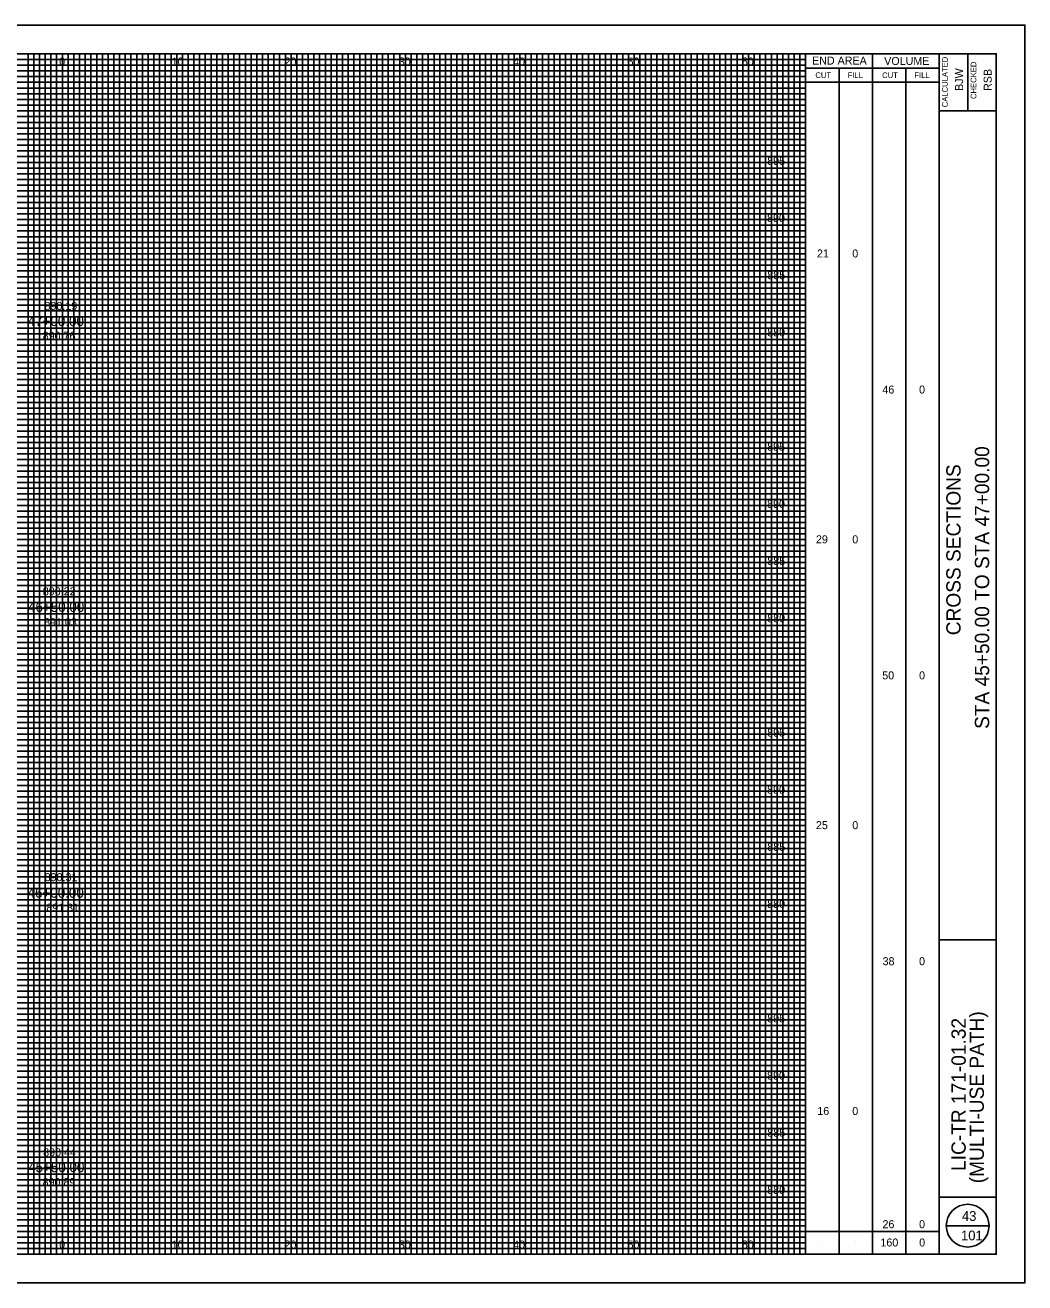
# Model space of a CAD drawing. Extents: x -10 to 160, y -2 to 2522.
# Drawn here: x 72.6 to 160, y 1722.5 to 1832.5 of the extents above; entities that cross this region are included whole.
import ezdxf

# ---------------------------------------------------------------- set-up
doc = ezdxf.new("R2010")
doc.units = 0
for name, color, linetype in [('GK_Cells', 7, 'Continuous'), ('GK_Patterns', 7, 'Continuous'), ('TX_P_10', 7, 'Continuous'), ('TX_X_10', 7, 'Continuous'), ('XS_P_Finished_Grade_Seeded', 7, 'Continuous'), ('XS_P_Pavt_Surface', 7, 'Continuous'), ('XS_P_Subgrade', 7, 'Continuous'), ('XS_X_Ground_Line', 7, 'Continuous')]:
    doc.layers.add(name, color=color, linetype=linetype)

msp = doc.modelspace()

# ---------------------------------------------------------------- linework, layer by layer
at = {"layer": 'GK_Cells'}
msp.add_lwpolyline([(-10, 1722.5), (160, 1722.5), (160, 1832.5), (-10, 1832.5)], close=True, dxfattribs=at)
at = {"layer": 'TX_P_10'}
for p, q in [((140.83, 1725), (140.83, 1830)), ((146.67, 1725), (146.67, 1830)), ((140.83, 1828.75), (152.5, 1828.75)), ((143.75, 1725), (143.75, 1828.75)), ((149.58, 1725), (149.58, 1828.75)), ((140.83, 1827.5), (152.5, 1827.5)), ((153.12, 1727.5), (156.88, 1727.5)), ((140.83, 1727), (152.5, 1727)), ((142.29, 1726), (142.29, 1726)), ((145.21, 1726), (145.21, 1726)), ((148.12, 1726), (148.12, 1726)), ((151.04, 1726), (151.04, 1726))]:
    msp.add_line(p, q, dxfattribs=at)
msp.add_circle((155, 1727.5), 1.87, dxfattribs=at)
at = {"layer": 'TX_X_10'}
for p, q in [((75.83, 1725), (75.83, 1830)), ((80.83, 1725), (80.83, 1830)), ((85.83, 1725), (85.83, 1830)), ((90.83, 1725), (90.83, 1830)), ((95.83, 1725), (95.83, 1830)), ((100.83, 1725), (100.83, 1830)), ((105.83, 1725), (105.83, 1830)), ((110.83, 1725), (110.83, 1830)), ((115.83, 1725), (115.83, 1830)), ((120.83, 1725), (120.83, 1830)), ((125.83, 1725), (125.83, 1830)), ((130.83, 1725), (130.83, 1830)), ((135.83, 1725), (135.83, 1830)), ((5.83, 1825), (140.83, 1825)), ((5.83, 1820), (140.83, 1820)), ((5.83, 1815), (140.83, 1815)), ((5.83, 1810), (140.83, 1810)), ((5.83, 1805), (140.83, 1805)), ((5.83, 1800), (140.83, 1800)), ((5.83, 1795), (140.83, 1795)), ((5.83, 1790), (140.83, 1790)), ((5.83, 1785), (140.83, 1785)), ((5.83, 1780), (140.83, 1780)), ((5.83, 1775), (140.83, 1775)), ((5.83, 1770), (140.83, 1770)), ((5.83, 1765), (140.83, 1765)), ((5.83, 1760), (140.83, 1760)), ((5.83, 1755), (140.83, 1755)), ((5.83, 1750), (140.83, 1750)), ((5.83, 1745), (140.83, 1745)), ((5.83, 1740), (140.83, 1740)), ((5.83, 1735), (140.83, 1735)), ((5.83, 1730), (140.83, 1730))]:
    msp.add_line(p, q, dxfattribs=at)
at = {"layer": 'XS_P_Pavt_Surface'}
for p, q in [((152.5, 1725), (152.5, 1830)), ((155, 1830), (155, 1825)), ((152.5, 1825), (157.5, 1825)), ((152.5, 1752.5), (157.5, 1752.5)), ((152.5, 1730), (157.5, 1730))]:
    msp.add_line(p, q, dxfattribs=at)
msp.add_lwpolyline([(0, 1830), (157.5, 1830), (157.5, 1725), (0, 1725)], close=True, dxfattribs=at)
at = {"layer": 'XS_X_Ground_Line'}
for p, q in [((5.83, 1829.5), (140.83, 1829.5)), ((72.83, 1725), (72.83, 1830)), ((73.33, 1725), (73.33, 1830)), ((73.83, 1725), (73.83, 1830)), ((74.33, 1725), (74.33, 1830)), ((74.83, 1725), (74.83, 1830)), ((75.33, 1725), (75.33, 1830)), ((76.33, 1725), (76.33, 1830)), ((76.83, 1725), (76.83, 1830)), ((77.33, 1725), (77.33, 1830)), ((77.83, 1725), (77.83, 1830)), ((78.33, 1725), (78.33, 1830)), ((78.83, 1725), (78.83, 1830)), ((79.33, 1725), (79.33, 1830)), ((79.83, 1725), (79.83, 1830)), ((80.33, 1725), (80.33, 1830)), ((81.33, 1725), (81.33, 1830)), ((81.83, 1725), (81.83, 1830)), ((82.33, 1725), (82.33, 1830)), ((82.83, 1725), (82.83, 1830)), ((83.33, 1725), (83.33, 1830)), ((83.83, 1725), (83.83, 1830)), ((84.33, 1725), (84.33, 1830)), ((84.83, 1725), (84.83, 1830)), ((85.33, 1725), (85.33, 1830)), ((86.33, 1725), (86.33, 1830)), ((86.83, 1725), (86.83, 1830)), ((87.33, 1725), (87.33, 1830)), ((87.83, 1725), (87.83, 1830)), ((88.33, 1725), (88.33, 1830)), ((88.83, 1725), (88.83, 1830)), ((89.33, 1725), (89.33, 1830)), ((89.83, 1725), (89.83, 1830)), ((90.33, 1725), (90.33, 1830)), ((91.33, 1725), (91.33, 1830)), ((91.83, 1725), (91.83, 1830)), ((92.33, 1725), (92.33, 1830)), ((92.83, 1725), (92.83, 1830)), ((93.33, 1725), (93.33, 1830)), ((93.83, 1725), (93.83, 1830)), ((94.33, 1725), (94.33, 1830)), ((94.83, 1725), (94.83, 1830)), ((95.33, 1725), (95.33, 1830)), ((96.33, 1725), (96.33, 1830)), ((96.83, 1725), (96.83, 1830)), ((97.33, 1725), (97.33, 1830)), ((97.83, 1725), (97.83, 1830)), ((98.33, 1725), (98.33, 1830)), ((98.83, 1725), (98.83, 1830)), ((99.33, 1725), (99.33, 1830)), ((99.83, 1725), (99.83, 1830)), ((100.33, 1725), (100.33, 1830)), ((101.33, 1725), (101.33, 1830)), ((101.83, 1725), (101.83, 1830)), ((102.33, 1725), (102.33, 1830)), ((102.83, 1725), (102.83, 1830)), ((103.33, 1725), (103.33, 1830)), ((103.83, 1725), (103.83, 1830)), ((104.33, 1725), (104.33, 1830)), ((104.83, 1725), (104.83, 1830)), ((105.33, 1725), (105.33, 1830)), ((106.33, 1725), (106.33, 1830)), ((106.83, 1725), (106.83, 1830)), ((107.33, 1725), (107.33, 1830)), ((107.83, 1725), (107.83, 1830)), ((108.33, 1725), (108.33, 1830)), ((108.83, 1725), (108.83, 1830)), ((109.33, 1725), (109.33, 1830)), ((109.83, 1725), (109.83, 1830)), ((110.33, 1725), (110.33, 1830)), ((111.33, 1725), (111.33, 1830)), ((111.83, 1725), (111.83, 1830)), ((112.33, 1725), (112.33, 1830)), ((112.83, 1725), (112.83, 1830)), ((113.33, 1725), (113.33, 1830)), ((113.83, 1725), (113.83, 1830)), ((114.33, 1725), (114.33, 1830)), ((114.83, 1725), (114.83, 1830)), ((115.33, 1725), (115.33, 1830)), ((116.33, 1725), (116.33, 1830)), ((116.83, 1725), (116.83, 1830)), ((117.33, 1725), (117.33, 1830)), ((117.83, 1725), (117.83, 1830)), ((118.33, 1725), (118.33, 1830)), ((118.83, 1725), (118.83, 1830)), ((119.33, 1725), (119.33, 1830)), ((119.83, 1725), (119.83, 1830)), ((120.33, 1725), (120.33, 1830)), ((121.33, 1725), (121.33, 1830)), ((121.83, 1725), (121.83, 1830)), ((122.33, 1725), (122.33, 1830)), ((122.83, 1725), (122.83, 1830)), ((123.33, 1725), (123.33, 1830)), ((123.83, 1725), (123.83, 1830)), ((124.33, 1725), (124.33, 1830)), ((124.83, 1725), (124.83, 1830)), ((125.33, 1725), (125.33, 1830)), ((126.33, 1725), (126.33, 1830)), ((126.83, 1725), (126.83, 1830)), ((127.33, 1725), (127.33, 1830)), ((127.83, 1725), (127.83, 1830)), ((128.33, 1725), (128.33, 1830)), ((128.83, 1725), (128.83, 1830)), ((129.33, 1725), (129.33, 1830)), ((129.83, 1725), (129.83, 1830)), ((130.33, 1725), (130.33, 1830)), ((131.33, 1725), (131.33, 1830)), ((131.83, 1725), (131.83, 1830)), ((132.33, 1725), (132.33, 1830)), ((132.83, 1725), (132.83, 1830)), ((133.33, 1725), (133.33, 1830)), ((133.83, 1725), (133.83, 1830)), ((134.33, 1725), (134.33, 1830)), ((134.83, 1725), (134.83, 1830)), ((135.33, 1725), (135.33, 1830)), ((136.33, 1725), (136.33, 1830)), ((136.83, 1725), (136.83, 1830)), ((137.33, 1725), (137.33, 1830)), ((137.83, 1725), (137.83, 1830)), ((138.33, 1725), (138.33, 1830)), ((138.83, 1725), (138.83, 1830)), ((139.33, 1725), (139.33, 1830)), ((139.83, 1725), (139.83, 1830)), ((140.33, 1725), (140.33, 1830)), ((5.83, 1829), (140.83, 1829)), ((5.83, 1828.5), (140.83, 1828.5)), ((5.83, 1828), (140.83, 1828)), ((5.83, 1827.5), (140.83, 1827.5)), ((5.83, 1827), (140.83, 1827)), ((5.83, 1826.5), (140.83, 1826.5)), ((5.83, 1826), (140.83, 1826)), ((5.83, 1825.5), (140.83, 1825.5)), ((5.83, 1824.5), (140.83, 1824.5)), ((5.83, 1824), (140.83, 1824)), ((5.83, 1823.5), (140.83, 1823.5)), ((5.83, 1823), (140.83, 1823)), ((5.83, 1822.5), (140.83, 1822.5)), ((5.83, 1822), (140.83, 1822)), ((5.83, 1821.5), (140.83, 1821.5)), ((5.83, 1821), (140.83, 1821)), ((5.83, 1820.5), (140.83, 1820.5)), ((5.83, 1819.5), (140.83, 1819.5)), ((5.83, 1819), (140.83, 1819)), ((5.83, 1818.5), (140.83, 1818.5)), ((5.83, 1818), (140.83, 1818)), ((5.83, 1817.5), (140.83, 1817.5)), ((5.83, 1817), (140.83, 1817)), ((5.83, 1816.5), (140.83, 1816.5)), ((5.83, 1816), (140.83, 1816)), ((5.83, 1815.5), (140.83, 1815.5)), ((5.83, 1814.5), (140.83, 1814.5)), ((5.83, 1814), (140.83, 1814)), ((5.83, 1813.5), (140.83, 1813.5)), ((5.83, 1813), (140.83, 1813)), ((5.83, 1812.5), (140.83, 1812.5)), ((5.83, 1812), (140.83, 1812)), ((5.83, 1811.5), (140.83, 1811.5)), ((5.83, 1811), (140.83, 1811)), ((5.83, 1810.5), (140.83, 1810.5)), ((5.83, 1809.5), (140.83, 1809.5)), ((5.83, 1809), (140.83, 1809)), ((5.83, 1808.5), (140.83, 1808.5)), ((5.83, 1808), (140.83, 1808)), ((5.83, 1807.5), (140.83, 1807.5)), ((5.83, 1807), (140.83, 1807)), ((5.83, 1806.5), (140.83, 1806.5)), ((5.83, 1806), (140.83, 1806)), ((5.83, 1805.5), (140.83, 1805.5)), ((5.83, 1804.5), (140.83, 1804.5)), ((5.83, 1804), (140.83, 1804)), ((5.83, 1803.5), (140.83, 1803.5)), ((5.83, 1803), (140.83, 1803)), ((5.83, 1802.5), (140.83, 1802.5)), ((5.83, 1802), (140.83, 1802)), ((5.83, 1801.5), (140.83, 1801.5)), ((5.83, 1801), (140.83, 1801)), ((5.83, 1800.5), (140.83, 1800.5)), ((5.83, 1799.5), (140.83, 1799.5)), ((5.83, 1799), (140.83, 1799)), ((5.83, 1798.5), (140.83, 1798.5)), ((5.83, 1798), (140.83, 1798)), ((5.83, 1797.5), (140.83, 1797.5)), ((5.83, 1797), (140.83, 1797)), ((5.83, 1796.5), (140.83, 1796.5)), ((5.83, 1796), (140.83, 1796)), ((5.83, 1795.5), (140.83, 1795.5)), ((5.83, 1794.5), (140.83, 1794.5)), ((5.83, 1794), (140.83, 1794)), ((5.83, 1793.5), (140.83, 1793.5)), ((5.83, 1793), (140.83, 1793)), ((5.83, 1792.5), (140.83, 1792.5)), ((5.83, 1792), (140.83, 1792)), ((5.83, 1791.5), (140.83, 1791.5)), ((5.83, 1791), (140.83, 1791)), ((5.83, 1790.5), (140.83, 1790.5)), ((5.83, 1789.5), (140.83, 1789.5)), ((5.83, 1789), (140.83, 1789)), ((5.83, 1788.5), (140.83, 1788.5)), ((5.83, 1788), (140.83, 1788)), ((5.83, 1787.5), (140.83, 1787.5)), ((5.83, 1787), (140.83, 1787)), ((5.83, 1786.5), (140.83, 1786.5)), ((5.83, 1786), (140.83, 1786)), ((5.83, 1785.5), (140.83, 1785.5)), ((5.83, 1784.5), (140.83, 1784.5)), ((5.83, 1784), (140.83, 1784)), ((5.83, 1783.5), (140.83, 1783.5)), ((5.83, 1783), (140.83, 1783)), ((5.83, 1782.5), (140.83, 1782.5)), ((5.83, 1782), (140.83, 1782)), ((5.83, 1781.5), (140.83, 1781.5)), ((5.83, 1781), (140.83, 1781)), ((5.83, 1780.5), (140.83, 1780.5)), ((5.83, 1779.5), (140.83, 1779.5)), ((5.83, 1779), (140.83, 1779)), ((5.83, 1778.5), (140.83, 1778.5)), ((5.83, 1778), (140.83, 1778)), ((5.83, 1777.5), (140.83, 1777.5)), ((5.83, 1777), (140.83, 1777)), ((5.83, 1776.5), (140.83, 1776.5)), ((5.83, 1776), (140.83, 1776)), ((5.83, 1775.5), (140.83, 1775.5)), ((5.83, 1774.5), (140.83, 1774.5)), ((5.83, 1774), (140.83, 1774)), ((5.83, 1773.5), (140.83, 1773.5)), ((5.83, 1773), (140.83, 1773)), ((5.83, 1772.5), (140.83, 1772.5)), ((5.83, 1772), (140.83, 1772)), ((5.83, 1771.5), (140.83, 1771.5)), ((5.83, 1771), (140.83, 1771)), ((5.83, 1770.5), (140.83, 1770.5)), ((5.83, 1769.5), (140.83, 1769.5)), ((5.83, 1769), (140.83, 1769)), ((5.83, 1768.5), (140.83, 1768.5)), ((5.83, 1768), (140.83, 1768)), ((5.83, 1767.5), (140.83, 1767.5)), ((5.83, 1767), (140.83, 1767)), ((5.83, 1766.5), (140.83, 1766.5)), ((5.83, 1766), (140.83, 1766)), ((5.83, 1765.5), (140.83, 1765.5)), ((5.83, 1764.5), (140.83, 1764.5)), ((5.83, 1764), (140.83, 1764)), ((5.83, 1763.5), (140.83, 1763.5)), ((5.83, 1763), (140.83, 1763)), ((5.83, 1762.5), (140.83, 1762.5)), ((5.83, 1762), (140.83, 1762)), ((5.83, 1761.5), (140.83, 1761.5)), ((5.83, 1761), (140.83, 1761)), ((5.83, 1760.5), (140.83, 1760.5)), ((5.83, 1759.5), (140.83, 1759.5)), ((5.83, 1759), (140.83, 1759)), ((5.83, 1758.5), (140.83, 1758.5)), ((5.83, 1758), (140.83, 1758)), ((5.83, 1757.5), (140.83, 1757.5)), ((5.83, 1757), (140.83, 1757)), ((5.83, 1756.5), (140.83, 1756.5)), ((5.83, 1756), (140.83, 1756)), ((5.83, 1755.5), (140.83, 1755.5)), ((5.83, 1754.5), (140.83, 1754.5)), ((5.83, 1754), (140.83, 1754)), ((5.83, 1753.5), (140.83, 1753.5)), ((5.83, 1753), (140.83, 1753)), ((5.83, 1752.5), (140.83, 1752.5)), ((5.83, 1752), (140.83, 1752)), ((5.83, 1751.5), (140.83, 1751.5)), ((5.83, 1751), (140.83, 1751)), ((5.83, 1750.5), (140.83, 1750.5)), ((5.83, 1749.5), (140.83, 1749.5)), ((5.83, 1749), (140.83, 1749)), ((5.83, 1748.5), (140.83, 1748.5)), ((5.83, 1748), (140.83, 1748)), ((5.83, 1747.5), (140.83, 1747.5)), ((5.83, 1747), (140.83, 1747)), ((5.83, 1746.5), (140.83, 1746.5)), ((5.83, 1746), (140.83, 1746)), ((5.83, 1745.5), (140.83, 1745.5)), ((5.83, 1744.5), (140.83, 1744.5)), ((5.83, 1744), (140.83, 1744)), ((5.83, 1743.5), (140.83, 1743.5)), ((5.83, 1743), (140.83, 1743)), ((5.83, 1742.5), (140.83, 1742.5)), ((5.83, 1742), (140.83, 1742)), ((5.83, 1741.5), (140.83, 1741.5)), ((5.83, 1741), (140.83, 1741)), ((5.83, 1740.5), (140.83, 1740.5)), ((5.83, 1739.5), (140.83, 1739.5)), ((5.83, 1739), (140.83, 1739)), ((5.83, 1738.5), (140.83, 1738.5)), ((5.83, 1738), (140.83, 1738)), ((5.83, 1737.5), (140.83, 1737.5)), ((5.83, 1737), (140.83, 1737)), ((5.83, 1736.5), (140.83, 1736.5)), ((5.83, 1736), (140.83, 1736)), ((5.83, 1735.5), (140.83, 1735.5)), ((5.83, 1734.5), (140.83, 1734.5)), ((5.83, 1734), (140.83, 1734)), ((5.83, 1733.5), (140.83, 1733.5)), ((5.83, 1733), (140.83, 1733)), ((5.83, 1732.5), (140.83, 1732.5)), ((5.83, 1732), (140.83, 1732)), ((5.83, 1731.5), (140.83, 1731.5)), ((5.83, 1731), (140.83, 1731)), ((5.83, 1730.5), (140.83, 1730.5)), ((5.83, 1729.5), (140.83, 1729.5)), ((5.83, 1729), (140.83, 1729)), ((5.83, 1728.5), (140.83, 1728.5)), ((5.83, 1728), (140.83, 1728)), ((5.83, 1727.5), (140.83, 1727.5)), ((5.83, 1727), (140.83, 1727)), ((5.83, 1726.5), (140.83, 1726.5)), ((5.83, 1726), (140.83, 1726)), ((5.83, 1725.5), (140.83, 1725.5))]:
    msp.add_line(p, q, dxfattribs=at)

# ---------------------------------------------------------------- texts
at = {"layer": 'GK_Patterns'}
for s, height, p in [('0', 0.7, (75.55, 1828.97)), ('0', 0.7, (75.55, 1828.97)), ('10', 0.7, (85.39, 1828.97)), ('20', 0.7, (95.26, 1828.97)), ('30', 0.7, (105.25, 1828.97)), ('40', 0.7, (115.25, 1828.97)), ('50', 0.7, (125.25, 1828.97)), ('60', 0.7, (135.25, 1828.97)), ('895', 0.7, (137.47, 1820.28)), ('890', 0.7, (137.46, 1815.28)), ('21', 0.7, (141.82, 1812.18)), ('0', 0.7, (144.91, 1812.18)), ('885', 0.7, (137.48, 1810.28)), ('47+00.00', 0.875, (72.8, 1806.18)), ('880', 0.7, (137.47, 1805.28)), ('46', 0.7, (147.54, 1800.28)), ('0', 0.7, (150.75, 1800.28)), ('895', 0.7, (137.47, 1795.28)), ('890', 0.7, (137.46, 1790.28)), ('29', 0.7, (141.73, 1787.18)), ('0', 0.7, (144.91, 1787.18)), ('885', 0.7, (137.48, 1785.28)), ('46+50.00', 0.875, (72.83, 1781.18)), ('880', 0.7, (137.47, 1780.28)), ('50', 0.7, (147.53, 1775.28)), ('0', 0.7, (150.75, 1775.28)), ('895', 0.7, (137.47, 1770.28)), ('890', 0.7, (137.46, 1765.28)), ('25', 0.7, (141.73, 1762.18)), ('0', 0.7, (144.91, 1762.18)), ('885', 0.7, (137.48, 1760.28)), ('46+00.00', 0.875, (72.79, 1756.18)), ('880', 0.7, (137.47, 1755.28)), ('38', 0.7, (147.56, 1750.28)), ('0', 0.7, (150.75, 1750.28)), ('895', 0.7, (137.47, 1745.28)), ('890', 0.7, (137.46, 1740.28)), ('16', 0.7, (141.85, 1737.18)), ('0', 0.7, (144.91, 1737.18)), ('885', 0.7, (137.48, 1735.28)), ('45+50.00', 0.875, (72.84, 1732.18)), ('880', 0.7, (137.47, 1730.28)), ('26', 0.7, (147.55, 1727.28)), ('0', 0.7, (150.75, 1727.28)), ('0', 0.7, (75.55, 1725.5)), ('0', 0.7, (75.55, 1725.5)), ('10', 0.7, (85.39, 1725.5)), ('20', 0.7, (95.26, 1725.5)), ('30', 0.7, (105.25, 1725.5)), ('40', 0.7, (115.25, 1725.5)), ('50', 0.7, (125.25, 1725.5)), ('60', 0.7, (135.25, 1725.5)), ('160', 0.7, (147.37, 1725.68)), ('0', 0.7, (150.76, 1725.68))]:
    msp.add_text(s, height=height, dxfattribs=at).set_placement(p)
at = {"layer": 'TX_P_10'}
for s, height, p in [('END AREA', 0.7, (141.39, 1829.05)), ('VOLUME', 0.7, (147.7, 1829.02)), ('CUT', 0.5, (141.68, 1827.87)), ('FILL', 0.5, (144.5, 1827.87)), ('CUT', 0.5, (147.52, 1827.87)), ('FILL', 0.5, (150.34, 1827.87)), ('43', 0.85, (154.5, 1727.92)), ('101', 0.85, (154.42, 1726.22))]:
    msp.add_text(s, height=height, dxfattribs=at).set_placement(p)
for s, height, p in [('CALCULATED', 0.5, (153.26, 1825.32)), ('BJW', 0.7, (154.6, 1826.75)), ('CHECKED', 0.5, (155.76, 1826.04)), ('RSB', 0.7, (157.1, 1826.75)), ('STA 45+50.00 TO STA 47+00.00', 1.25, (156.88, 1770.95)), ('CROSS SECTIONS', 1.25, (154.38, 1779.14)), ('(MULTI-USE PATH)', 1.25, (156.42, 1731.21)), ('LIC-TR 171-01.32', 1.25, (154.83, 1732.29))]:
    msp.add_text(s, height=height, rotation=90, dxfattribs=at).set_placement(p)
at = {"layer": 'XS_P_Finished_Grade_Seeded'}
for s, p in [('890.76', (74.11, 1804.98)), ('891.03', (74.23, 1779.93)), ('891.31', (74.42, 1754.97)), ('890.89', (74.1, 1730.96))]:
    msp.add_text(s, height=0.7, dxfattribs=at).set_placement(p)
at = {"layer": 'XS_P_Subgrade'}
for s, p in [('890.19', (74.27, 1807.59)), ('890.22', (74.12, 1782.63)), ('890.31', (74.28, 1757.63)), ('890.44', (74.15, 1733.57))]:
    msp.add_text(s, height=0.7, dxfattribs=at).set_placement(p)

doc.saveas('drawing.dxf')
